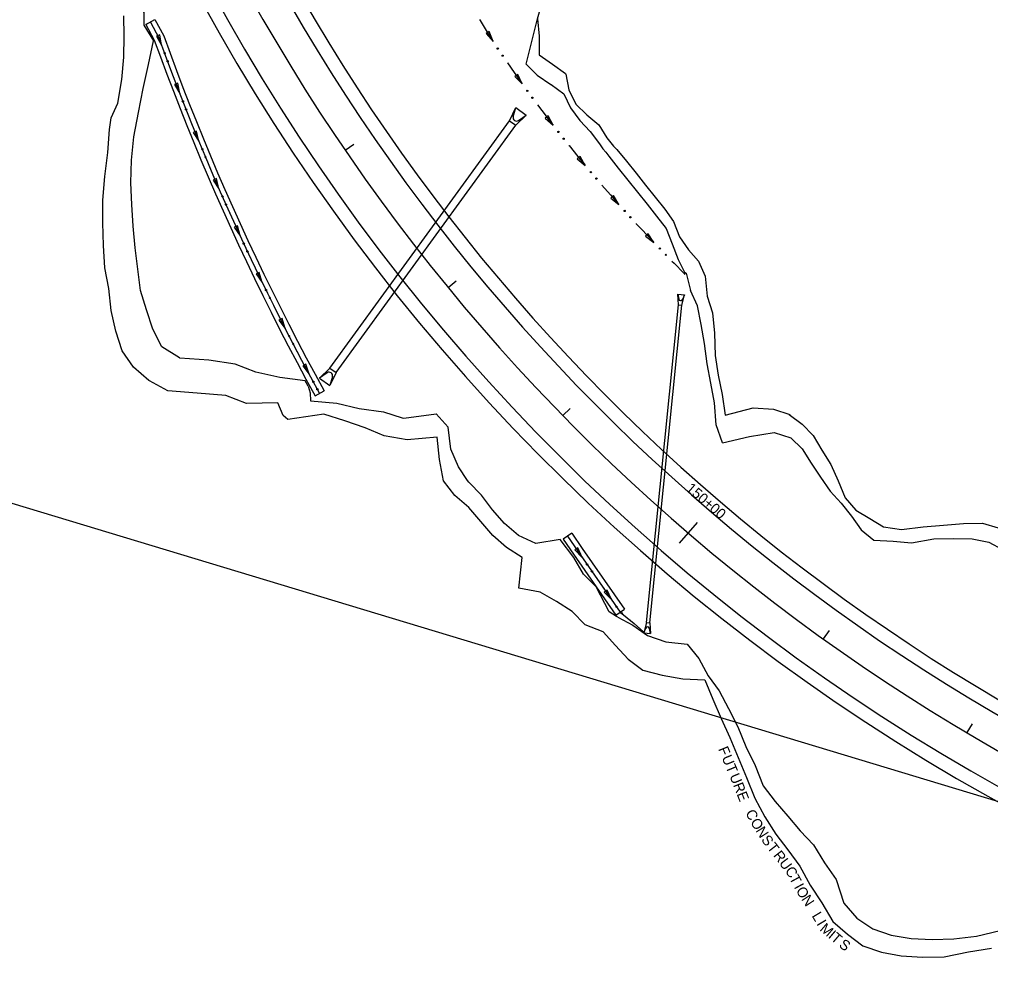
# Model space of a CAD drawing. Extents: x 979959 to 994833, y 1835619 to 1845316.
# Drawn here: x 980596 to 981161, y 1838457 to 1839009 of the extents above; entities that cross this region are included whole.
import ezdxf

# ---------------------------------------------------------------- set-up
doc = ezdxf.new("R2010")
doc.units = 0
for name, color, linetype in [('Future 5 Lane Construction Limits', 7, 'Continuous'), ('R_CONCRETE', 7, 'Continuous'), ('R_Drainage', 7, 'Continuous'), ('R_Horz Alg', 7, 'Continuous'), ('R_Horz Alg Annot_Side Road', 7, 'Continuous'), ('R_Horz Alg Stationing', 7, 'Continuous'), ('R_Proposed Const Limits', 7, 'Continuous'), ('R_Proposed Road', 7, 'Continuous'), ('R_Special Ditch', 7, 'Continuous')]:
    doc.layers.add(name, color=color, linetype=linetype)

msp = doc.modelspace()

# ---------------------------------------------------------------- linework, layer by layer
at = {"layer": 'Future 5 Lane Construction Limits'}
for points in [[(980935.55, 1838651.82), (980924.92, 1838655.86), (980917.43, 1838663.54), (980908.37, 1838669.46), (980898.77, 1838674.82), (980886.36, 1838677.26), (980888.38, 1838695.01), (980879.17, 1838700.83), (980871.2, 1838707.96), (980864.21, 1838716.07), (980857.28, 1838724.23), (980849.18, 1838731.23), (980842.55, 1838739.66), (980840.26, 1838752.09), (980838.87, 1838765.18), (980821.31, 1838763.59), (980807.96, 1838766.04), (980796.87, 1838770.64), (980785.09, 1838774.77), (980772.81, 1838778.64), (980751.83, 1838775.52), (980749.1, 1838777.76), (980746.09, 1838785.09), (980727.79, 1838784.69), (980715.7, 1838789.43), (980699.05, 1838790.84), (980681.99, 1838792.21), (980671.19, 1838798.02), (980670.9, 1838798.26), (980661.92, 1838805.95), (980655.39, 1838815.43), (980651.62, 1838826.83), (980648.94, 1838838.91), (980647.52, 1838851.74), (980645.26, 1838863.89), (980644.49, 1838876.9), (980644.07, 1838890), (980644.13, 1838903.26), (980645.19, 1838916.99), (980646.91, 1838930.95), (980647.91, 1838944.31), (980648.88, 1838951.19), (980652.73, 1838959.71), (980655.11, 1838973.51), (980656.36, 1838986.5), (980656.5, 1838998.75), (980656.22, 1839010.65)], [(980897.3, 1839008.77), (980898.25, 1838998.69), (980898.3, 1838987.86), (980905.93, 1838982.38), (980913.52, 1838976.93), (980913.66, 1838976.69), (980915.58, 1838967.4), (980919.54, 1838959.23), (980926.05, 1838953.01), (980933.04, 1838947.18), (980937.61, 1838939.46), (980941.44, 1838934.7), (980943.36, 1838932.67), (980949.07, 1838925.86), (980954.66, 1838918.94), (980960.21, 1838911.98), (980965.74, 1838904.99), (980971.36, 1838898.08), (980976.49, 1838890.71), (980979.98, 1838881.78), (980985.11, 1838874.32), (980991.1, 1838867.66), (980994.92, 1838858.87), (980996.04, 1838847.3), (980999.24, 1838837.66), (981000.37, 1838825.77), (981000.66, 1838812.79), (981002.56, 1838801.31), (981004.8, 1838790.01), (981006.61, 1838778.06), (981022.95, 1838782.26), (981034.68, 1838781.54), (981044.13, 1838778.37)], [(981043.84, 1838778.47), (981051.37, 1838772.68), (981057.83, 1838766.05), (981062.85, 1838757.62), (981068.04, 1838749.31), (981072.32, 1838739.75), (981076.47, 1838729.89), (981082.7, 1838722.61), (981090.76, 1838717.74), (981098.86, 1838712.95), (981109.32, 1838711.48), (981121.79, 1838713.02), (981133.7, 1838713.99), (981145.36, 1838714.85), (981156.47, 1838715.1), (981165.53, 1838712.42)], [(980935.55, 1838651.82), (980942.76, 1838643.83), (980950, 1838635.85), (980958.52, 1838629.38), (980969.87, 1838626.46), (980981.81, 1838624.44), (980994.66, 1838623.77)], [(980994.66, 1838623.77), (980999.37, 1838612.56), (981004.21, 1838601.33), (981009.34, 1838590.32), (981014.13, 1838578.67), (981019.03, 1838566.96), (981023.79, 1838554.86), (981029.6, 1838544.07), (981035.99, 1838533.98), (981043.09, 1838524.81), (981050.09, 1838515.36), (981056.12, 1838504.25), (981062.77, 1838493.92), (981069.24, 1838483.12), (981077.86, 1838475.74), (981086.82, 1838468.9), (981097.59, 1838465.18), (981109.16, 1838462.96), (981121.49, 1838462.28), (981134.15, 1838462.42), (981148.21, 1838465.44), (981161.59, 1838467.5)]]:
    msp.add_lwpolyline(points, dxfattribs=at)
at = {"layer": 'R_CONCRETE'}
for p, q in [((980669.11, 1839005.54), (980674.38, 1839008.42)), ((980767.69, 1838789.26), (980772.96, 1838792.13)), ((980917.19, 1838709.23), (980912.24, 1838705.85)), ((980942.93, 1838661.58), (980947.86, 1838665.01))]:
    msp.add_line(p, q, dxfattribs=at)
for points in [[(980674.38, 1839008.42), (980679.53, 1838999), (980683.25, 1838988.79), (980686.96, 1838978.82), (980690.76, 1838968.86), (980694.63, 1838958.91), (980698.59, 1838948.97), (980702.63, 1838939.05), (980706.75, 1838929.14), (980710.95, 1838919.24), (980715.23, 1838909.36), (980719.59, 1838899.49), (980724.03, 1838889.64), (980728.55, 1838879.81), (980733.16, 1838869.99), (980737.85, 1838860.19), (980742.62, 1838850.41), (980747.47, 1838840.65), (980752.4, 1838830.91), (980757.42, 1838821.19), (980762.51, 1838811.48), (980767.69, 1838801.8), (980772.96, 1838792.13)], [(980669.11, 1839005.54), (980674.05, 1838996.52), (980677.62, 1838986.72), (980681.35, 1838976.7), (980685.16, 1838966.7), (980689.05, 1838956.71), (980693.02, 1838946.73), (980697.08, 1838936.76), (980701.21, 1838926.81), (980705.43, 1838916.88), (980709.73, 1838906.95), (980714.11, 1838897.05), (980718.57, 1838887.16), (980723.11, 1838877.28), (980727.74, 1838867.42), (980732.44, 1838857.59), (980737.23, 1838847.76), (980742.1, 1838837.96), (980747.06, 1838828.18), (980752.09, 1838818.42), (980757.21, 1838808.67), (980762.41, 1838798.95), (980767.69, 1838789.26)], [(980917.19, 1838709.23), (980923.22, 1838700.41), (980947.86, 1838665.01)], [(980912.24, 1838705.85), (980918.28, 1838697), (980942.93, 1838661.58)]]:
    msp.add_lwpolyline(points, dxfattribs=at)
at = {"layer": 'R_Drainage'}
for p, q in [((980880.95, 1838949.49), (980884.63, 1838957.11)), ((980883.1, 1838951.83), (980884.63, 1838957.11)), ((980884.63, 1838957.11), (980890.7, 1838952.71)), ((980884.59, 1838946.85), (980890.7, 1838952.71)), ((980886.15, 1838949.62), (980890.7, 1838952.71)), ((980776.38, 1838805.45), (980880.95, 1838949.49)), ((980780.02, 1838802.81), (980884.59, 1838946.85)), ((980880.95, 1838949.49), (980884.59, 1838946.85)), ((980978.9, 1838848.52), (980982.88, 1838848.12)), ((980979.28, 1838842.33), (980978.9, 1838848.52)), ((980978.9, 1838848.52), (980979.51, 1838845.64)), ((980981.27, 1838842.13), (980982.88, 1838848.12)), ((980982.88, 1838848.12), (980981.71, 1838845.42)), ((980960.71, 1838657.26), (980979.28, 1838842.33)), ((980979.28, 1838842.33), (980981.27, 1838842.13)), ((980962.7, 1838657.06), (980981.27, 1838842.13)), ((980776.38, 1838805.45), (980770.27, 1838799.59)), ((980774.82, 1838802.69), (980770.27, 1838799.59)), ((980780.02, 1838802.81), (980776.34, 1838795.19)), ((980776.38, 1838805.45), (980780.02, 1838802.81)), ((980770.27, 1838799.59), (980776.34, 1838795.19)), ((980777.87, 1838800.48), (980776.34, 1838795.19)), ((980960.71, 1838657.26), (980959.11, 1838651.27)), ((980960.71, 1838657.26), (980962.7, 1838657.06)), ((980962.7, 1838657.06), (980963.09, 1838650.87)), ((980959.11, 1838651.27), (980960.27, 1838653.96)), ((980959.11, 1838651.27), (980963.09, 1838650.87)), ((980963.09, 1838650.87), (980962.48, 1838653.74))]:
    msp.add_line(p, q, dxfattribs=at)
for centre, radius, start, end in [((980885.02, 1838951.28), 2, 163.8614, 304.1785), ((980980.64, 1838845.88), 1.17, 191.8001, 336.7402), ((980775.94, 1838801.03), 2, 343.8614, 124.1785), ((980961.34, 1838653.51), 1.17, 11.8001, 156.7402)]:
    msp.add_arc(centre, radius, start, end, dxfattribs=at)
at = {"layer": 'R_Horz Alg'}
msp.add_arc((981731.15, 1839579.08), 1145.92, 152.21752, 253.16792, dxfattribs=at)
at = {"layer": 'R_Horz Alg Annot_Side Road'}
msp.add_line((980069.95, 1838884.43), (981399.33, 1838482.26), dxfattribs=at)
at = {"layer": 'R_Horz Alg Stationing'}
for points in [[(980790.25, 1838935.56), (980785.3, 1838932.17)], [(980849.92, 1838856), (980845.28, 1838852.2)], [(980916.29, 1838781.95), (980912, 1838777.75)], [(980990.17, 1838715.48), (980979.75, 1838703.34)], [(981067.09, 1838652.56), (981063.59, 1838647.68)], [(981150.37, 1838598.21), (981147.31, 1838593.05)]]:
    msp.add_lwpolyline(points, dxfattribs=at)
at = {"layer": 'R_Proposed Const Limits'}
for p, q in [((980671.75, 1839006.98), (980669.11, 1839005.54)), ((980926.87, 1838689.91), (980945.4, 1838663.3)), ((980944.03, 1838660.3), (980943.19, 1838660.73))]:
    msp.add_line(p, q, dxfattribs=at)
for points in [[(980890.66, 1838982.44), (980897.3, 1839008.77), (980900.86, 1839021.78), (980911.49, 1839039.23), (980913.72, 1839050.87), (980916.42, 1839062.64), (980916.91, 1839072.85), (980915.52, 1839081.8), (980912.18, 1839089.52), (980907.55, 1839096.46), (980905.12, 1839099.43)], [(980649.97, 1839066.5), (980654.08, 1839056.78), (980656.52, 1839046.33), (980659.06, 1839035.88), (980661.99, 1839025.59), (980665.91, 1839015.78), (980667.95, 1839012.47), (980667.94, 1839005.26), (980673.63, 1838996.02)], [(980671.75, 1839006.98), (980676.79, 1838997.76), (980680.43, 1838987.76), (980684.15, 1838977.76), (980687.96, 1838967.78), (980691.84, 1838957.81), (980695.81, 1838947.85), (980699.85, 1838937.91), (980703.98, 1838927.97), (980708.19, 1838918.06), (980712.48, 1838908.16), (980716.85, 1838898.27), (980721.3, 1838888.4), (980725.83, 1838878.55), (980730.45, 1838868.71), (980735.15, 1838858.89), (980739.92, 1838849.09), (980744.79, 1838839.31), (980749.73, 1838829.54), (980754.75, 1838819.8), (980759.86, 1838810.08), (980765.05, 1838800.38), (980770.33, 1838790.7)], [(980763.69, 1838794.83), (980761.99, 1838797.91), (980747.12, 1838799.99), (980733.16, 1838803.01), (980721.12, 1838807.69), (980705.86, 1838810.11), (980689.01, 1838811.15), (980688.68, 1838811.35), (980678.4, 1838817.86), (980673.15, 1838828.03), (980669.48, 1838839.28), (980666.06, 1838850.62), (980664.4, 1838863.06), (980662.83, 1838875.46), (980661.71, 1838888.02), (980661.04, 1838900.76), (980660.42, 1838913.39), (980660.82, 1838926.52), (980662.1, 1838940.03), (980664.91, 1838954.27), (980666.19, 1838961.24), (980667.54, 1838968.22), (980670.61, 1838982.23), (980673.63, 1838996.02)], [(980890.66, 1838982.44), (980897.1, 1838976), (980905.04, 1838970.69), (980905.29, 1838970.52), (980912.6, 1838965.16), (980916.53, 1838956.94), (980921.83, 1838949.72), (980928.02, 1838943.21), (980933.38, 1838936.05), (980935.28, 1838933.19), (980937.1, 1838931.16), (980938.81, 1838928.94), (980944.32, 1838921.89), (980949.85, 1838914.85), (980955.45, 1838907.86), (980961.07, 1838900.89), (980966.65, 1838893.86), (980972.19, 1838886.79), (980975.7, 1838877.81), (980979.15, 1838868.7), (980982.96, 1838861.29), (980983.84, 1838860.68), (980986.4, 1838850.53)], [(981004.91, 1838761.96), (981001.4, 1838772.31), (981000.34, 1838785.17), (980998.14, 1838796.6), (980995.98, 1838807.89), (980994.57, 1838819.79), (980992.52, 1838830.85), (980990.38, 1838841.67), (980986.4, 1838850.53)], [(980757.21, 1838815.12), (980757.23, 1838815.09)], [(980763.69, 1838794.83), (980764.91, 1838790.99), (980765.04, 1838786.36), (980780.34, 1838784.93), (980793.43, 1838781.86), (980807.56, 1838779.89), (980818.47, 1838776.5), (980819.48, 1838776.19), (980838.2, 1838778.73), (980845.3, 1838771.04)], [(980910.5, 1838705.65), (980896.25, 1838703.27), (980886.11, 1838707.98), (980878.04, 1838714.89), (980871.11, 1838722.94), (980864.68, 1838731.46), (980857.3, 1838739.04), (980856.45, 1838739.92), (980851.27, 1838747.89), (980846.81, 1838758.16), (980845.3, 1838771.04)], [(981004.91, 1838761.96), (981020.76, 1838765.61), (981035.17, 1838767.92)], [(981035.17, 1838767.92), (981044.8, 1838764.88), (981051.41, 1838758.3), (981056.6, 1838749.94), (981062.03, 1838741.79), (981067.62, 1838733.76), (981074.02, 1838726.71), (981080.04, 1838719.1), (981085.85, 1838711.14), (981093.23, 1838705.24), (981104.42, 1838704.64), (981115.13, 1838703.56), (981128.17, 1838705.99), (981139.52, 1838706.23), (981150.32, 1838705.86), (981160.05, 1838704.02), (981168.17, 1838699.79), (981175.18, 1838693.83), (981181.72, 1838687.04), (981188.14, 1838680), (981193.58, 1838671.19), (981198.03, 1838660.51), (981202.41, 1838649.48), (981205.18, 1838635.27)], [(980914.72, 1838707.54), (980920.75, 1838698.7), (980926.87, 1838689.91)], [(980943.19, 1838660.73), (980939.07, 1838663.48), (980931.5, 1838678.01), (980924.06, 1838685.43), (980918.36, 1838695.16), (980910.5, 1838705.65)], [(980931.78, 1838682.86), (980931.8, 1838682.83)], [(980945.4, 1838663.3), (980953.57, 1838656.66), (980959.02, 1838651.75), (980959.19, 1838651.59)], [(980944.03, 1838660.3), (980952.71, 1838655.63), (980961.41, 1838649.62)], [(980950.21, 1838659.39), (980950.24, 1838659.36)], [(980961.41, 1838649.62), (980971.95, 1838645.89)], [(980971.95, 1838645.89), (980984.37, 1838644.61)], [(980984.37, 1838644.61), (980991.15, 1838636.34), (980996.56, 1838626.23), (981003.02, 1838617.37), (981008.46, 1838607.05), (981013.86, 1838596.52), (981018.66, 1838584.99), (981023.94, 1838573.95), (981028.71, 1838561.98), (981035.66, 1838553.01), (981042.98, 1838544.48), (981050.3, 1838535.85), (981057.99, 1838527.7), (981064.32, 1838517.3), (981071.19, 1838507.59), (981075.64, 1838493.72), (981083.28, 1838484.91), (981092.57, 1838478.8), (981103.23, 1838475.09), (981114.84, 1838473.17), (981127.13, 1838472.61), (981139.75, 1838472.9), (981152.91, 1838474.42), (981166.82, 1838477.72)]]:
    msp.add_lwpolyline(points, dxfattribs=at)
at = {"layer": 'R_Proposed Road'}
for radius, start in [(1127.92, 152.21752), (1119.92, 152.21752), (1171.92, 188.09242), (1163.92, 189.25012)]:
    msp.add_arc((981731.15, 1839579.08), radius, start, 253.16792, dxfattribs=at)
at = {"layer": 'R_Special Ditch'}
for p, q in [((980869.08, 1839001.38), (980867.28, 1839000.26)), ((980871.36, 1838995.73), (980869.08, 1839001.38)), ((980677.27, 1838999.54), (980675.28, 1838998.82)), ((980675.28, 1838998.82), (980678.32, 1838993.54)), ((980678.32, 1838993.54), (980677.27, 1838999.54)), ((980867.28, 1839000.26), (980871.36, 1838995.73)), ((980885.74, 1838976.47), (980884.01, 1838975.25)), ((980884.01, 1838975.25), (980888.36, 1838970.97)), ((980888.36, 1838970.97), (980885.74, 1838976.47)), ((980687.71, 1838971.39), (980685.74, 1838970.64)), ((980685.74, 1838970.64), (980688.86, 1838965.41)), ((980688.86, 1838965.41), (980687.71, 1838971.39)), ((980903.5, 1838952.29), (980901.81, 1838951.01)), ((980901.81, 1838951.01), (980906.29, 1838946.88)), ((980906.29, 1838946.88), (980903.5, 1838952.29)), ((980698.73, 1838943.48), (980696.77, 1838942.68)), ((980696.77, 1838942.68), (980700.01, 1838937.52)), ((980700.01, 1838937.52), (980698.73, 1838943.48)), ((980922.07, 1838928.74), (980920.44, 1838927.39)), ((980920.44, 1838927.39), (980925.07, 1838923.44)), ((980925.07, 1838923.44), (980922.07, 1838928.74)), ((980710.32, 1838915.79), (980708.38, 1838914.95)), ((980711.74, 1838909.87), (980710.32, 1838915.79)), ((980708.38, 1838914.95), (980711.74, 1838909.87)), ((980941.48, 1838905.86), (980939.89, 1838904.46)), ((980939.89, 1838904.46), (980944.66, 1838900.67)), ((980944.66, 1838900.67), (980941.48, 1838905.86)), ((980722.49, 1838888.35), (980720.56, 1838887.47)), ((980720.56, 1838887.47), (980724.03, 1838882.46)), ((980724.03, 1838882.46), (980722.49, 1838888.35)), ((980961.67, 1838883.67), (980960.13, 1838882.22)), ((980960.13, 1838882.22), (980965.01, 1838878.57)), ((980965.01, 1838878.57), (980961.67, 1838883.67)), ((980735.21, 1838861.17), (980733.31, 1838860.24)), ((980733.31, 1838860.24), (980736.89, 1838855.31)), ((980736.89, 1838855.31), (980735.21, 1838861.17)), ((980748.53, 1838834.26), (980746.64, 1838833.31)), ((980746.64, 1838833.31), (980750.29, 1838828.43)), ((980750.29, 1838828.43), (980748.53, 1838834.26)), ((980762.37, 1838807.63), (980760.51, 1838806.64)), ((980760.51, 1838806.64), (980764.27, 1838801.84)), ((980764.27, 1838801.84), (980762.37, 1838807.63)), ((980920.65, 1838700.7), (980918.91, 1838699.49)), ((980918.91, 1838699.49), (980923.21, 1838695.17)), ((980923.21, 1838695.17), (980920.65, 1838700.7)), ((980937.81, 1838676.05), (980936.07, 1838674.84)), ((980936.07, 1838674.84), (980940.37, 1838670.52)), ((980940.37, 1838670.52), (980937.81, 1838676.05))]:
    msp.add_line(p, q, dxfattribs=at)
for points in [[(980671.75, 1839006.98), (980676.79, 1838997.76), (980678.32, 1838993.54)], [(980863.51, 1839008.51), (980863.88, 1839007.88), (980868.61, 1839000.13), (980871.36, 1838995.73)], [(980683.52, 1838979.47), (980683.53, 1838979.43)], [(980683.53, 1838979.43), (980684.15, 1838977.76), (980687.96, 1838967.78), (980688.88, 1838965.42)], [(980879.69, 1838983.26), (980879.72, 1838983.23)], [(980879.72, 1838983.23), (980883.71, 1838977.5), (980888.36, 1838970.97)], [(980897.24, 1838958.84), (980899.72, 1838955.51), (980905.21, 1838948.29), (980906.3, 1838946.89)], [(980694.37, 1838951.46), (980694.38, 1838951.43)], [(980694.38, 1838951.42), (980695.81, 1838947.85), (980699.85, 1838937.91), (980700.01, 1838937.52)], [(980915.58, 1838935.1), (980915.6, 1838935.07)], [(980915.6, 1838935.07), (980916.42, 1838934.03), (980922.14, 1838926.99), (980924.35, 1838924.31), (980925.07, 1838923.44)], [(980705.8, 1838923.68), (980705.82, 1838923.65)], [(980705.82, 1838923.65), (980708.19, 1838918.06), (980711.74, 1838909.87)], [(980934.76, 1838911.98), (980934.78, 1838911.95)], [(980934.78, 1838911.95), (980939.73, 1838906.24), (980944.66, 1838900.67)], [(980717.81, 1838896.15), (980717.82, 1838896.11)], [(980717.82, 1838896.11), (980721.3, 1838888.4), (980724.03, 1838882.46)], [(980954.74, 1838889.56), (980954.76, 1838889.53)], [(980954.76, 1838889.53), (980957.96, 1838886.07), (980964.17, 1838879.47), (980965.02, 1838878.58)], [(980730.37, 1838868.87), (980730.39, 1838868.83)], [(980730.39, 1838868.83), (980730.45, 1838868.71), (980735.15, 1838858.89), (980736.89, 1838855.31)], [(980975.44, 1838867.79), (980975.46, 1838867.76)], [(980975.46, 1838867.76), (980976.76, 1838866.44), (980982.39, 1838860.75), (980983.13, 1838860)], [(980743.52, 1838841.86), (980743.53, 1838841.82)], [(980743.53, 1838841.82), (980744.79, 1838839.31), (980749.73, 1838829.54), (980750.3, 1838828.44)], [(980757.23, 1838815.09), (980759.86, 1838810.08), (980764.27, 1838801.84)], [(980914.72, 1838707.54), (980920.75, 1838698.7), (980923.21, 1838695.17)], [(980931.8, 1838682.83), (980940.37, 1838670.52)], [(980950.24, 1838659.36), (980953.57, 1838656.66), (980959.02, 1838651.75), (980959.19, 1838651.59)]]:
    msp.add_lwpolyline(points, dxfattribs=at)
for centre in [(980874.08, 1838991.53), (980680.07, 1838988.85), (980681.81, 1838984.15), (980876.9, 1838987.39), (980891.32, 1838966.94), (980690.73, 1838960.77), (980894.27, 1838962.89), (980692.56, 1838956.1), (980909.4, 1838942.96), (980912.5, 1838939.02), (980701.97, 1838932.91), (980703.89, 1838928.29), (980928.31, 1838919.62), (980931.55, 1838915.8), (980713.78, 1838905.3), (980715.81, 1838900.71), (980948.03, 1838896.97), (980951.39, 1838893.25), (980726.16, 1838877.93), (980728.29, 1838873.39), (980968.51, 1838874.99), (980971.98, 1838871.39), (980739.12, 1838850.83), (980741.33, 1838846.34), (980752.63, 1838824), (980754.93, 1838819.55), (980766.68, 1838797.46), (980769.08, 1838793.06), (980926.1, 1838691.08), (980928.96, 1838686.97), (980943.26, 1838666.43), (980946.36, 1838662.56)]:
    msp.add_circle(centre, 0.375, dxfattribs=at)

# ---------------------------------------------------------------- texts
at = {"layer": 'Future 5 Lane Construction Limits'}
for s, rotation, p in [('F', 292.3592, (981002.39, 1838583.56)), ('U', 292.3592, (981004.44, 1838578.58)), ('T', 292.7068, (981006.65, 1838573.22)), ('U', 292.7068, (981008.91, 1838567.82)), ('R', 291.4943, (981011.07, 1838562.61)), ('E', 291.4943, (981013.15, 1838557.33)), ('C', 298.2874, (981018.16, 1838546.35)), ('O', 302.3323, (981020.94, 1838540.92)), ('N', 302.3323, (981024.08, 1838535.97)), ('S', 307.7427, (981027.24, 1838530.58)), ('T', 307.7427, (981030.71, 1838526.1)), ('R', 307.7427, (981034.29, 1838521.46)), ('U', 306.5377, (981037.64, 1838517.04)), ('C', 306.5377, (981041.07, 1838512.41)), ('T', 298.4948, (981043.65, 1838508.35)), ('I', 298.4948, (981046.45, 1838503.2)), ('O', 302.7933, (981047.51, 1838501)), ('N', 302.7933, (981050.68, 1838496.08)), ('L', 300.9151, (981056.8, 1838486.38)), ('I', 300.9151, (981059.57, 1838481.75)), ('M', 319.4232, (981061.27, 1838478.1)), ('I', 319.4232, (981066.15, 1838473.92)), ('T', 319.4232, (981067.65, 1838472.63)), ('S', 322.6242, (981072.37, 1838468.61))]:
    msp.add_text(s, height=6, rotation=rotation, dxfattribs=at).set_placement(p)
at = {"layer": 'R_Horz Alg Stationing'}
msp.add_text('150+00', height=6, rotation=319.3699, dxfattribs=at).set_placement((980983.29, 1838734.56))

doc.saveas('drawing.dxf')
